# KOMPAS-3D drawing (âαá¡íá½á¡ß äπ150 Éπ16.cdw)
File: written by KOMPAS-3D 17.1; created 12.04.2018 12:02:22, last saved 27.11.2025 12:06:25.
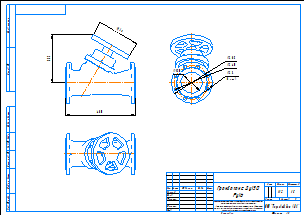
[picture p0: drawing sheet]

Sheet 1: A3, landscape

Title block, sheet 1: name: Гранбаланс Ду150 / Ру16; material: Сталь 20  ГОСТ 1050-88; mass: 112; sheets: 1; sheet format: A3; stored path: C:\Users\kka\KOMPAS_Work\!Trash\КМ125 КМ127 КМ225Ф Двухходовые клапана\КМ125Ф + PSL\KOMPAS 2D\Гранрег КМ125Ф Ду32 Ру16.cdw

Views: Спереди 1, Спереди, Проекционный вид 2, Проекционный вид 3
Referenced files in C:\Users\mipv\Desktop\КБЧ\Имеющиеся\: Гранбаланс Ду150 Ру16  серия 10.m3d
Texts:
  kka
  adl
  Рама для чертежей
  Лит-Масса-Масштаб
  Материал-Предприятие
  Масштаб
  Изм.
  Лист
  № докум.
  Подп.
  Дата
  Лит.
  Разраб.
  Пров.
  Т.контр.
  Листов
  Внимание! Данный продукт является объектом авторского права ООО «Торговый Дом АДЛ».
  Запрещается изменение, копирование, распространение
  (в том числе путем копирования на другие сайты и ресурсы в Интернете)
  или любое иное использование информации и объектов без предварительного
  согласия правообладателя (ООО «Торговый Дом АДЛ»).
  Н.контр.
  Утв.
  ООО "Торговый дом АДЛ"
  Изменение
  Номер документа
  Подпись
  Обозначение документа
  Наименование изделия
  Масса изделия по ГОСТ 2.109-73
  Порядковый номер листа
  Общее количество листов в документе
  Характер работы, выполненной лицом, подписавшим документ
  Наименование или индекс предприятия, выпускающего документ
  Инв. № подл.
  Подп. и дата
  Взам. инв. №
  Инв. № дубл.
  Инвентарный номер подлинника по ГОСТ 2.501-68
  Подпись принявшего подлинник в отдел технической документации
  Инвентарный номер подлинника, взамен которого выпущен данный подлинник
  Инвентарный номер дубликата по ГОСТ 2.502-68
  Подпись принявшего дубликат в отдел технической документации
  Справ. №
  Перв. примен.
  Обозначение документа, взамен или на основании которого выпущен данный документ
  Обозначение документа, в котором впервые записан данный документ
  Подпись лица, копировавшего чертеж
  Обозначение формата листа
  !Рама для чертежа
Dimensions and other numbers on the sheet: 480; 332; 290; 285; 240; 150; 23; 8 отв.; 1:5; 1; 112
